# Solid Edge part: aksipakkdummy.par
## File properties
Author: morva
Template: iso metric part.par
Last saved by: morva
Revision: 9
Application: Solid Edge
Density: 2070.16803087702 kg/m^3
Accuracy: 0.990
Username: morva
Material: Silicone
Face Style: White (clear)
Fill Style: Flexible Material
Virtual Style: Flexible Material
Grouping: Non-metals\Silicons
LibraryName: Materials
Coef. of Thermal Exp: 8.1e-05
Thermal Conductivity: 0.2
Specific Heat: 0.0
Modulus of Elasticity: 0.0
Poisson's Ratio: 0.28
Yield Stress: 0.0
Ultimate Stress: 0.0
Elongation: 0.0
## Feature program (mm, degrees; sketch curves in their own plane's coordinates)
sketch for "unnamed Protrusion 1" plane through (0, 0, 0) normal (0, 0, 1) x-axis (1, 0, 0)
  line (-40, 24.5) -> (40, 24.5)
  line (40, 24.5) -> (40, -24.5)
  line (40, -24.5) -> (-40, -24.5)
  line (-40, -24.5) -> (-40, 24.5)
  dimension (linear) = 40
  dimension (linear) = 40
extrude "unnamed Protrusion 1" add finite 292 along +normal
sketch for "ExtrudedProtrusion_2" #1 plane through (0, 0, 292) normal (0, 0, 1) x-axis (1, 0, 0)
  circle centre (-26, 10) radius 2.5
sketch for "ExtrudedProtrusion_2" #2 plane through (0, 0, 292) normal (0, 0, 1) x-axis (1, 0, 0)
  circle centre (-20, 10) radius 2.5
extrude "ExtrudedProtrusion_2" add finite 10 along +normal
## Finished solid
Body 1: solid body, 10 faces, 16 edges, 8 vertices.
  Faces by surface: plane 8, cylinder 2
  Edges by curve: line 12, circle 4
Bounding box of the edges (mm): 80.000 x 49.000 x 302.000, from (-40, -24.5, 0) to (40, 24.5, 302).
Cylindrical faces by radius (mm): R2.5 x2
Planar faces by outward normal: +x 1, +y 1, +z 3, -x 1, -y 1, -z 1
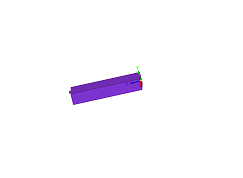
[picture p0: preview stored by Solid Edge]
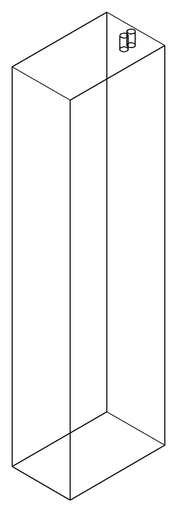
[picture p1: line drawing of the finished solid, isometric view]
